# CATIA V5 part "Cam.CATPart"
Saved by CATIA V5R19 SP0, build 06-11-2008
Part number: Cam
Bounding box of the stored display mesh (mm): x -10 to 60, y -35 to 35, z -50 to 30
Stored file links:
  D:\Shriniwas\v5_r19\c16_CAT_v5r19\c16_Part\Cam_Follower_msm_trial\Cam.CATPart
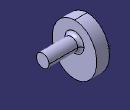
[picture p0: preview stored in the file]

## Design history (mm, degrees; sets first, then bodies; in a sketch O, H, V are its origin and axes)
Body1 (main body)
  Sketch1 on yz-plane, origin (0, 0, 0), H (0, 1, 0), V (0, 0, 1)
    point P1 (0, -10)
    ellipse A1 centre (0, -10) semi-axes 40, 35 rotation 90
    point P2 (0, 30)
    "Radius" A1 = 40
    distance V A1 = 35
    distance P1 H = 10
    coincidence: P1 V, P2 V, A1 P2
  Pad1: profile Sketch1, direction (1, 0, 0), length 10, mirrored extent
  Sketch2 on end face of Pad1, origin (10, 0, 0), H (0, 1, 0), V (0, 0, 1)
    circle A1 centre (0, 0) radius 10
    radius A1 = 10
  Pad2: profile Sketch2, direction (1, 0, 0), length 50
  Sketch3 on start face of Pad1, origin (-10, 0, 0), H (0, -1, 0), V (0, 0, 1)
    point P1 (-33.8886, 0)
    reference projected curve E1 from edge [start face of Pad1 | face of Pad1 from Sketch1.A1]
    coincidence: P1 H, P1 E1
  Fillet1: radius 5, on edge [end face of Pad1 | face of Pad2 from Sketch2.A1]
